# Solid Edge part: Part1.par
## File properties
Author: Deepak Maini
Template: normal.par
Last saved by: MYPC
Revision: 3
Application: Solid Edge
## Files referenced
..\Asm2.asm
=D:\sld-edg-15\cd-models\c09-sld-edg-15\figure9-11&12\Asm2.asm
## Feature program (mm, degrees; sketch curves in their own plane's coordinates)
sketch for "unnamed Protrusion 1" #1 plane through (0, 0, 0) normal (0, 0, 1) x-axis (1, 0, 0)
  line (-53.424, 13.2886) -> (-4.9489, 23.498)
  arc centre (0, 0) radius 24.0135 from (-4.9489, 23.498) to (4.9424, 23.4994) cw
  line (4.9424, 23.4994) -> (57.7581, 12.3911)
  arc centre (55.152, 0) radius 12.6622 from (57.7581, 12.3911) to (57.7581, -12.3911) cw
  line (57.7581, -12.3911) -> (4.9424, -23.4994)
  arc centre (0, 0) radius 24.0135 from (4.9424, -23.4994) to (-4.9489, -23.498) cw
  line (-53.424, -13.2886) -> (-4.9489, -23.498)
  arc centre (-50.6253, 0) radius 13.5802 from (-53.424, -13.2886) to (-53.424, 13.2886) cw
sketch for "unnamed Protrusion 1" #2 plane through (0, 0, 0) normal (0, 0, 1) x-axis (1, 0, 0)
  circle centre (-50.6253, 0) radius 7
sketch for "unnamed Protrusion 1" #3 plane through (0, 0, 0) normal (0, 0, 1) x-axis (1, 0, 0)
  circle centre (54.576, 0) radius 7
extrude "unnamed Protrusion 1" add finite 12.7 symmetric
sketch for "unnamed Protrusion 2" plane through (1.8044, 0, 12.7) normal (0, 0, 1) x-axis (0.97859, 0.205819, 0)
  circle centre (-1.7657, 0.3714) radius 14.0039
extrude "unnamed Protrusion 2" add through along -normal
sketch for "unnamed Hole 1" plane through (0, 0, 12.7) normal (0, 0, 1) x-axis (0, 1, 0)
  hole centre (0, 0) bore radius 9
hole "unnamed Hole 1" through
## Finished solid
Body 1: solid body, 15 faces, 32 edges, 16 vertices.
  Faces by surface: cylinder 8, plane 7
  Edges by curve: circle 16, line 16
Bounding box of the edges (mm): 132.020 x 48.027 x 19.050, from (-64.2054, -24.0135, -6.35) to (67.8142, 24.0135, 12.7).
Cylindrical faces by radius (mm): R7 x2, R9 x1, R12.6622 x1, R13.5802 x1, R14.0039 x1, R24.0135 x2
Planar faces by outward normal: +z 2, -z 1, oblique 4
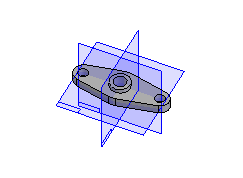
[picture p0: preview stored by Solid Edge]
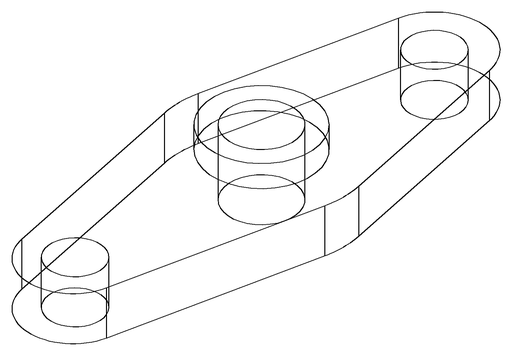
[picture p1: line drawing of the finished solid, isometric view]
